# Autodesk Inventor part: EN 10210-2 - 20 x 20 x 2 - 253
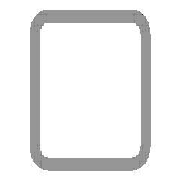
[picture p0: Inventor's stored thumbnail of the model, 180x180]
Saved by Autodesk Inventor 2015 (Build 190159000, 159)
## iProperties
Created: 2015-05
Part Number: EN 10210-2 - 20 x 20 x 2 - 253
Material: Steel, Mild
Description: Tube
Document SubType Name: Modeling
Standard: DIN
Designer: TREINA6
Standard Revision: 1997
Standards Organization: DIN
Language: en-US
Size Designation: 20 x 20 x 2
Categories: <MemberInstance><Categories><Category DisplayName="Structural Shapes" InternalName="089c4875-fa83-4c05-b084-43b9cc11f5ed" Mnemonic="GRDR"><CategoryParameter Dis
Stock Number: 20 x 20 x 2
Density: 7.85 g/cm^3
Appearance: Semi-Polished
_CCFamilyMember: 1
_CCFamilyDisplayName: DIN EN 10210-2 (Square) - Tube
_FrameMemberDoc: Frame Member File
_Version: 15.0.0
_GetPNFromCC: 1
IsCustomPart: 1
Author: TREINA6
G_L: 253,000 mm
G_W: 20,000 mm
G_H: 20,000 mm
+416ED0BE-771C-4462-B551-5CEA9B5C91F3+CUTDETAIL1: Miter 45,00 deg
+6D4B1D60-CFD2-41F1-9A60-DCD532D67BE1+CUTDETAIL2: Miter 45,00 deg
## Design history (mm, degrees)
node "Start plane"
node "End plane"
sketch "Sketch"
  geometry: L1 (-10, -7)-(-10, 7); L2 (-7, 10)-(7, 10); L3 (10, 7)-(10, -7); L4 (7, -10)-(-7, -10); L5 (-7, 8)-(7, 8); L6 (8, 7)-(8, -7); L7 (7, -8)-(-7, -8); L8 (-8, -7)-(-8, 7); L9 (0, 14.87)-(0, -14.87) reference; L10 (-14.87, 0)-(14.87, 0) reference; A1 r 3 centre (-7, -7) between (-10, -7) and (-7, -10); A2 r 3 centre (-7, 7) between (-7, 10) and (-10, 7); A3 r 3 centre (7, 7) between (10, 7) and (7, 10); A4 r 3 centre (7, -7) between (7, -10) and (10, -7); A5 r 1 centre (-7, 7) between (-7, 8) and (-8, 7); A6 r 1 centre (7, 7) between (8, 7) and (7, 8); A7 r 1 centre (7, -7) between (7, -8) and (8, -7); A8 r 1 centre (-7, -7) between (-8, -7) and (-7, -8)
  constraints: 16 end point, 16 point on circle, 8 centre point, 8 tangent, 4 parallel, 3 equal radius, 2 perpendicular, 7 other
  dimensions: "d7" = 3 radius of A1 (= G_IR); "d10" = 20 distance between parallel lines of L2 L4 (= G_H); "d11" = 20 distance between parallel lines of L1 L3 (= G_W); "d12" = 2 distance between parallel lines of L3 L6 (= G_T); "d15" = 10 distance between parallel lines of L2 L10 (= 0.5 x d10); "d16" = 10 distance between parallel lines of L9 L3 (= 0.5 x d11)
extrude "Body" new body sketch "Sketch" stored distance "d3" = 253 (= G_L); taper "d4" = 0 deg
node "Driven Length"
  sketch "Sketch3"
    geometry: L1 (0, 0)-(10, 0) reference
    constraints: 2 end point, 1 horizontal
  workplane "Work Plane3"
  sketch "Sketch4"
    geometry: L1 (-2, 0)-(12, 0) reference; L2 (-2, 253)-(12, 253) reference
    dimensions: "d18" = 253 distance between parallel lines of L1 L2 (derived)
workplane "Work Plane4"
split "Split1"
workplane "Work Plane5"
split "Split2"
body "Solid1"
other parameters: "G_W" = 20 [user parameter; used in 1 equation term], "G_H" = 20 [user parameter; used in 1 equation term], "G_T" = 2 [user parameter; used in 1 equation term], "G_IR" = 3 [user parameter; used in 1 equation term], "G_L" = 253 (= d18) [user parameter; used in 1 equation term], "G_OFFSET_START" = 0 [user parameter; used in 1 equation term], "G_OFFSET_END" = 0 [user parameter; used in 1 equation term], "d13" = 0 (computed from G_OFFSET_START), "d14" = 253 (= G_OFFSET_END + B_L), "B_L" = 253 [user parameter; used in 1 equation term], "d17" = 90 deg
